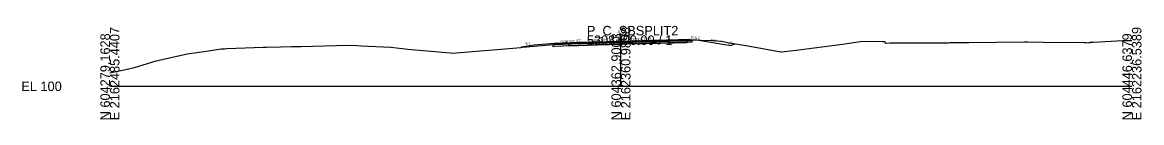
# Model space of a CAD drawing. Extents: x -26 to 1303, y -10 to 12033.
# Drawn here: x 974.3 to 1302.8, y 1990.3 to 2017.8 of the extents above; entities that cross this region are included whole.
import ezdxf

# ---------------------------------------------------------------- set-up
doc = ezdxf.new("R2010")
doc.units = 0
for name, color, linetype in [('RD_GPK_XS_Cell', 7, 'Continuous'), ('RD_XS_Base', 7, 'Continuous'), ('RD_XS_ExGround', 7, 'Continuous'), ('RD_XS_ExPaveRet', 7, 'Continuous'), ('RD_XS_Greenside', 7, 'Continuous'), ('RD_XS_Pave', 7, 'Continuous'), ('RD_XS_PaveOvlay_CP', 7, 'Continuous'), ('RD_XS_TieSlope', 7, 'Continuous'), ('RD_XS_TX_Elev_EX', 7, 'Continuous'), ('RD_XS_TX_Elev_PR', 7, 'Continuous'), ('RD_XS_TX_ShdSlope', 7, 'Continuous'), ('RD_XS_TX_Slope', 7, 'Continuous')]:
    doc.layers.add(name, color=color, linetype=linetype)

msp = doc.modelspace()

# ---------------------------------------------------------------- linework, layer by layer
at = {"layer": 'RD_GPK_XS_Cell'}
for p, q in [((1150, 2000), (1150, 2015)), ((1000, 2000), (1150, 2000)), ((1150, 2000), (1300, 2000))]:
    msp.add_line(p, q, dxfattribs=at)
at = {"layer": 'RD_XS_Base'}
for p, q in [((1130.55, 2012.3), (1130.05, 2012.28)), ((1130.05, 2012.28), (1130.05, 2012.28)), ((1130.05, 2012.28), (1130.05, 2011.78)), ((1130.05, 2011.78), (1130.55, 2011.8)), ((1138, 2012.59), (1130.55, 2012.3)), ((1130.55, 2012.3), (1130.55, 2012.3)), ((1130.55, 2011.8), (1138, 2012.09)), ((1130.55, 2011.8), (1130.55, 2011.8)), ((1150, 2012.93), (1138, 2012.59)), ((1138, 2012.59), (1138, 2012.59)), ((1138, 2012.09), (1150, 2012.43)), ((1138, 2012.09), (1138, 2012.09)), ((1150, 2012.93), (1170.27, 2013.5)), ((1150, 2012.43), (1150, 2013.09)), ((1150, 2013.09), (1150, 2013.09)), ((1150, 2013.09), (1150, 2013.09)), ((1150, 2013.09), (1150, 2012.93)), ((1170.77, 2013.01), (1150, 2012.43)), ((1150, 2012.93), (1150, 2012.93)), ((1150, 2012.43), (1150, 2012.93)), ((1150, 2012.93), (1150, 2012.93)), ((1150, 2012.93), (1150, 2012.93)), ((1150, 2012.43), (1150, 2012.43)), ((1162, 2013.27), (1162, 2013.27)), ((1162, 2013.27), (1162, 2013.27)), ((1162, 2012.77), (1162, 2012.77)), ((1162, 2012.77), (1162, 2012.77)), ((1170.27, 2013.5), (1170.27, 2013.5)), ((1170.77, 2013.51), (1170.77, 2013.01)), ((1170.77, 2013.48), (1170.77, 2013.48))]:
    msp.add_line(p, q, dxfattribs=at)
at = {"layer": 'RD_XS_ExGround'}
msp.add_lwpolyline([(1000, 2003.98), (1004.1, 2004.87), (1007.19, 2005.55), (1008.44, 2005.9), (1013.54, 2007.5), (1022.26, 2009.45), (1022.63, 2009.53), (1028.4, 2010.37), (1032.67, 2011.02), (1033.09, 2011.07), (1033.65, 2011.09), (1034.35, 2011.12), (1044.99, 2011.5), (1045.83, 2011.5), (1050.08, 2011.63), (1053.31, 2011.73), (1053.67, 2011.7), (1055.01, 2011.74), (1056.07, 2011.78), (1066.5, 2012.06), (1068.84, 2012.14), (1072.7, 2011.98), (1073.75, 2011.96), (1082.46, 2011.56), (1087.43, 2010.98), (1098.82, 2009.92), (1100.81, 2009.74), (1101.78, 2009.84), (1120.61, 2011.48), (1120.82, 2011.5), (1121.15, 2011.53), (1134.66, 2012.71), (1143.1, 2012.97), (1150.23, 2013.19), (1150.48, 2013.2), (1153.45, 2013.32), (1154.01, 2013.3), (1157.24, 2013.41), (1158.81, 2013.44), (1160.74, 2013.48), (1161.72, 2013.5), (1169.48, 2013.66), (1177.37, 2013.51), (1179.32, 2013.32), (1179.49, 2013.29), (1181.91, 2012.81), (1187.79, 2011.8), (1196.91, 2010.18), (1197.01, 2010.16), (1197.11, 2010.17), (1201.47, 2010.7), (1215.06, 2012.45), (1220.9, 2013.28), (1226.74, 2013.25), (1227.46, 2013.25), (1227.47, 2013.22), (1227.61, 2012.75), (1227.68, 2012.75), (1229.02, 2012.8), (1229.71, 2012.79), (1232.34, 2012.78), (1246.12, 2012.84), (1246.58, 2012.87), (1247.88, 2012.9), (1252.09, 2012.95), (1268.36, 2013.14), (1268.95, 2013.14), (1269.3, 2013.15), (1273.93, 2013.05), (1286.11, 2012.9), (1286.54, 2012.88), (1287.53, 2012.85), (1287.57, 2012.9), (1287.64, 2012.94), (1287.65, 2012.96), (1288.24, 2012.99), (1288.31, 2012.99), (1288.67, 2013), (1297.35, 2013.49), (1298.56, 2013.47), (1299.8, 2013.53), (1300, 2013.53)], dxfattribs=at)
at = {"layer": 'RD_XS_ExPaveRet'}
for points in [[(1169.48, 2013.66), (1169.48, 2013.66), (1169.48, 2013.66), (1169.48, 2012.91), (1169.48, 2012.91), (1161.72, 2012.75), (1161.72, 2012.75), (1160.74, 2012.73), (1160.74, 2012.73), (1158.81, 2012.69), (1157.24, 2012.66), (1157.24, 2012.66), (1154.01, 2012.55), (1153.45, 2012.57), (1153.45, 2012.57), (1150.48, 2012.45), (1150.48, 2012.45), (1150.48, 2012.45), (1150.23, 2012.44), (1143.1, 2012.22), (1143.1, 2012.22), (1134.66, 2011.96), (1134.66, 2011.96), (1134.66, 2012.71), (1134.66, 2012.71), (1134.66, 2012.71), (1143.1, 2012.97), (1143.1, 2012.97), (1150.23, 2013.19), (1150.48, 2013.2), (1150.48, 2013.2), (1150.48, 2013.2), (1153.45, 2013.32), (1153.45, 2013.32), (1154.01, 2013.3), (1157.24, 2013.41), (1157.24, 2013.41), (1158.81, 2013.44), (1160.74, 2013.48), (1160.74, 2013.48), (1161.72, 2013.5), (1161.72, 2013.5), (1169.48, 2013.66)], [(1161.72, 2013.5), (1160.74, 2013.48), (1158.81, 2013.44), (1157.24, 2013.41), (1154.01, 2013.3), (1153.45, 2013.32), (1150.48, 2013.2), (1150.23, 2013.19), (1143.1, 2012.97), (1134.66, 2012.71), (1134.66, 2011.96), (1143.1, 2012.22), (1150.23, 2012.44), (1150.48, 2012.45), (1153.45, 2012.57), (1154.01, 2012.55), (1157.24, 2012.66), (1158.81, 2012.69), (1160.74, 2012.73), (1161.72, 2012.75), (1169.48, 2012.91), (1169.48, 2013.66), (1161.72, 2013.5)]]:
    msp.add_lwpolyline(points, dxfattribs=at)
at = {"layer": 'RD_XS_Greenside'}
for p, q in [((1124.55, 2012.14), (1120.67, 2011.49)), ((1172.27, 2013.66), (1182.27, 2011.99)), ((1182.27, 2011.99), (1183.4, 2012.55))]:
    msp.add_line(p, q, dxfattribs=at)
at = {"layer": 'RD_XS_Pave'}
for p, q in [((1138, 2012.91), (1130.55, 2012.62)), ((1130.55, 2012.46), (1138, 2012.75)), ((1138, 2012.75), (1130.55, 2012.46)), ((1130.55, 2012.62), (1130.55, 2012.62)), ((1130.55, 2012.62), (1130.55, 2012.46)), ((1130.55, 2012.3), (1138, 2012.59)), ((1130.55, 2012.46), (1130.55, 2012.46)), ((1130.55, 2012.46), (1130.55, 2012.3)), ((1150, 2013.25), (1138, 2012.91)), ((1138, 2012.75), (1150, 2013.09)), ((1150, 2013.09), (1138, 2012.75)), ((1138, 2012.59), (1150, 2012.93)), ((1138, 2012.91), (1138, 2012.91)), ((1138, 2012.75), (1138, 2012.75)), ((1138, 2012.75), (1138, 2012.75)), ((1138, 2012.59), (1138, 2012.59)), ((1170.27, 2013.82), (1150, 2013.25)), ((1170.27, 2013.66), (1150, 2013.09)), ((1150, 2013.09), (1170.27, 2013.66)), ((1150, 2012.93), (1170.77, 2013.51)), ((1150, 2013.25), (1150, 2013.25)), ((1150, 2013.09), (1150, 2013.09)), ((1150, 2013.09), (1150, 2013.09)), ((1150, 2013.09), (1150, 2012.93)), ((1150, 2013.09), (1150, 2013.09)), ((1150, 2012.93), (1150, 2013.09)), ((1150, 2013.09), (1150, 2013.09)), ((1150, 2013.09), (1150, 2013.09)), ((1150, 2012.93), (1150, 2012.93)), ((1150, 2012.93), (1150, 2012.93)), ((1162, 2013.59), (1162, 2013.59)), ((1162, 2013.59), (1162, 2013.59)), ((1162, 2013.43), (1162, 2013.43)), ((1162, 2013.43), (1162, 2013.43)), ((1162, 2013.43), (1162, 2013.43)), ((1162, 2013.43), (1162, 2013.43)), ((1162, 2013.27), (1162, 2013.27)), ((1162, 2013.27), (1162, 2013.27)), ((1170.27, 2013.66), (1170.27, 2013.82)), ((1170.27, 2013.82), (1170.27, 2013.82)), ((1170.27, 2013.5), (1170.27, 2013.66)), ((1170.27, 2013.66), (1170.27, 2013.66))]:
    msp.add_line(p, q, dxfattribs=at)
at = {"layer": 'RD_XS_PaveOvlay_CP'}
for p, q in [((1138, 2012.91), (1130.55, 2012.62)), ((1150, 2013.25), (1138, 2012.91)), ((1138, 2012.91), (1138, 2012.91)), ((1162, 2013.59), (1150, 2013.25)), ((1150, 2013.25), (1150, 2013.25)), ((1162, 2013.59), (1162, 2013.59)), ((1162, 2013.59), (1162, 2013.59))]:
    msp.add_line(p, q, dxfattribs=at)
at = {"layer": 'RD_XS_TieSlope'}
for p, q in [((1130.55, 2012.62), (1124.55, 2012.14)), ((1170.27, 2013.82), (1172.27, 2013.66))]:
    msp.add_line(p, q, dxfattribs=at)

# ---------------------------------------------------------------- texts
at = {"layer": 'RD_GPK_XS_Cell'}
for s, p in [('E 2162485.4407', (1002.8, 1990)), ('E 2162360.9898', (1152.8, 1990)), ('E 2162236.5389', (1302.8, 1990)), ('N 604279.1628', (1000, 1990)), ('N 604362.9003', (1150, 1990)), ('N 604446.6379', (1300, 1990))]:
    msp.add_text(s, height=2.8, rotation=90, dxfattribs=at).set_placement(p)
for s, p in [('P_C_SBSPLIT2', (1140, 2015)), ('5308+00.00 / 1', (1140, 2012.2)), ('EL 100', (974, 1998.6))]:
    msp.add_text(s, height=2.8, dxfattribs=at).set_placement(p)
at = {"layer": 'RD_XS_TX_Elev_EX'}
msp.add_text('113.18', height=0.6, rotation=90, dxfattribs=at).set_placement((1149.61, 2013.97))
at = {"layer": 'RD_XS_TX_Elev_PR'}
msp.add_text('113.25', height=1, rotation=90, dxfattribs=at).set_placement((1151.25, 2013.57))
at = {"layer": 'RD_XS_TX_ShdSlope'}
msp.add_text('12.5:1', height=0.75, rotation=355.4261, dxfattribs=at).set_placement((1170.28, 2014.07))
at = {"layer": 'RD_XS_TX_Slope'}
for s, rotation, p in [('0.030 FT./FT.', 1.7184, (1140.41, 2013.18)), ('0.030 FT./FT.', 1.7184, (1153.16, 2013.45)), ('6:1', 350.5358, (1176.4, 2013.28)), ('6:1', 9.4623, (1122.07, 2012.15)), ('0.040 FT./FT.', 2.2906, (1132.31, 2012.76)), ('2:1', 26.5651, (1181.62, 2012.01))]:
    msp.add_text(s, height=0.75, rotation=rotation, dxfattribs=at).set_placement(p)

doc.saveas('drawing.dxf')
